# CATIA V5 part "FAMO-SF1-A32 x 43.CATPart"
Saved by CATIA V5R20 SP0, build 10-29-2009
Part number: FAMO-SF1-A32 x 43
Definition: NONE
Nomenclature: FAMO-SF1-A32 x 43
Source: Unknown
Description: FAMO-SF1-A32 x 43
Bounding box of the stored display mesh (mm): x -13 to 30, y -26.5 to 26.5, z -26.5 to 26.5
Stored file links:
  C:\Users\Utente\Desktop\IO LAVORO\3D X SITO CF\X SITO\FAMO\FAMO-SF1-A32 x 43.CATPart

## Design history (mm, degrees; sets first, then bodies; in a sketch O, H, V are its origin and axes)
Body1 "FAMO-SF1-A32 x 43" (main body)
  Solid1: solid without history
